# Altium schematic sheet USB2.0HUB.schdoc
size 311 x 219 mm
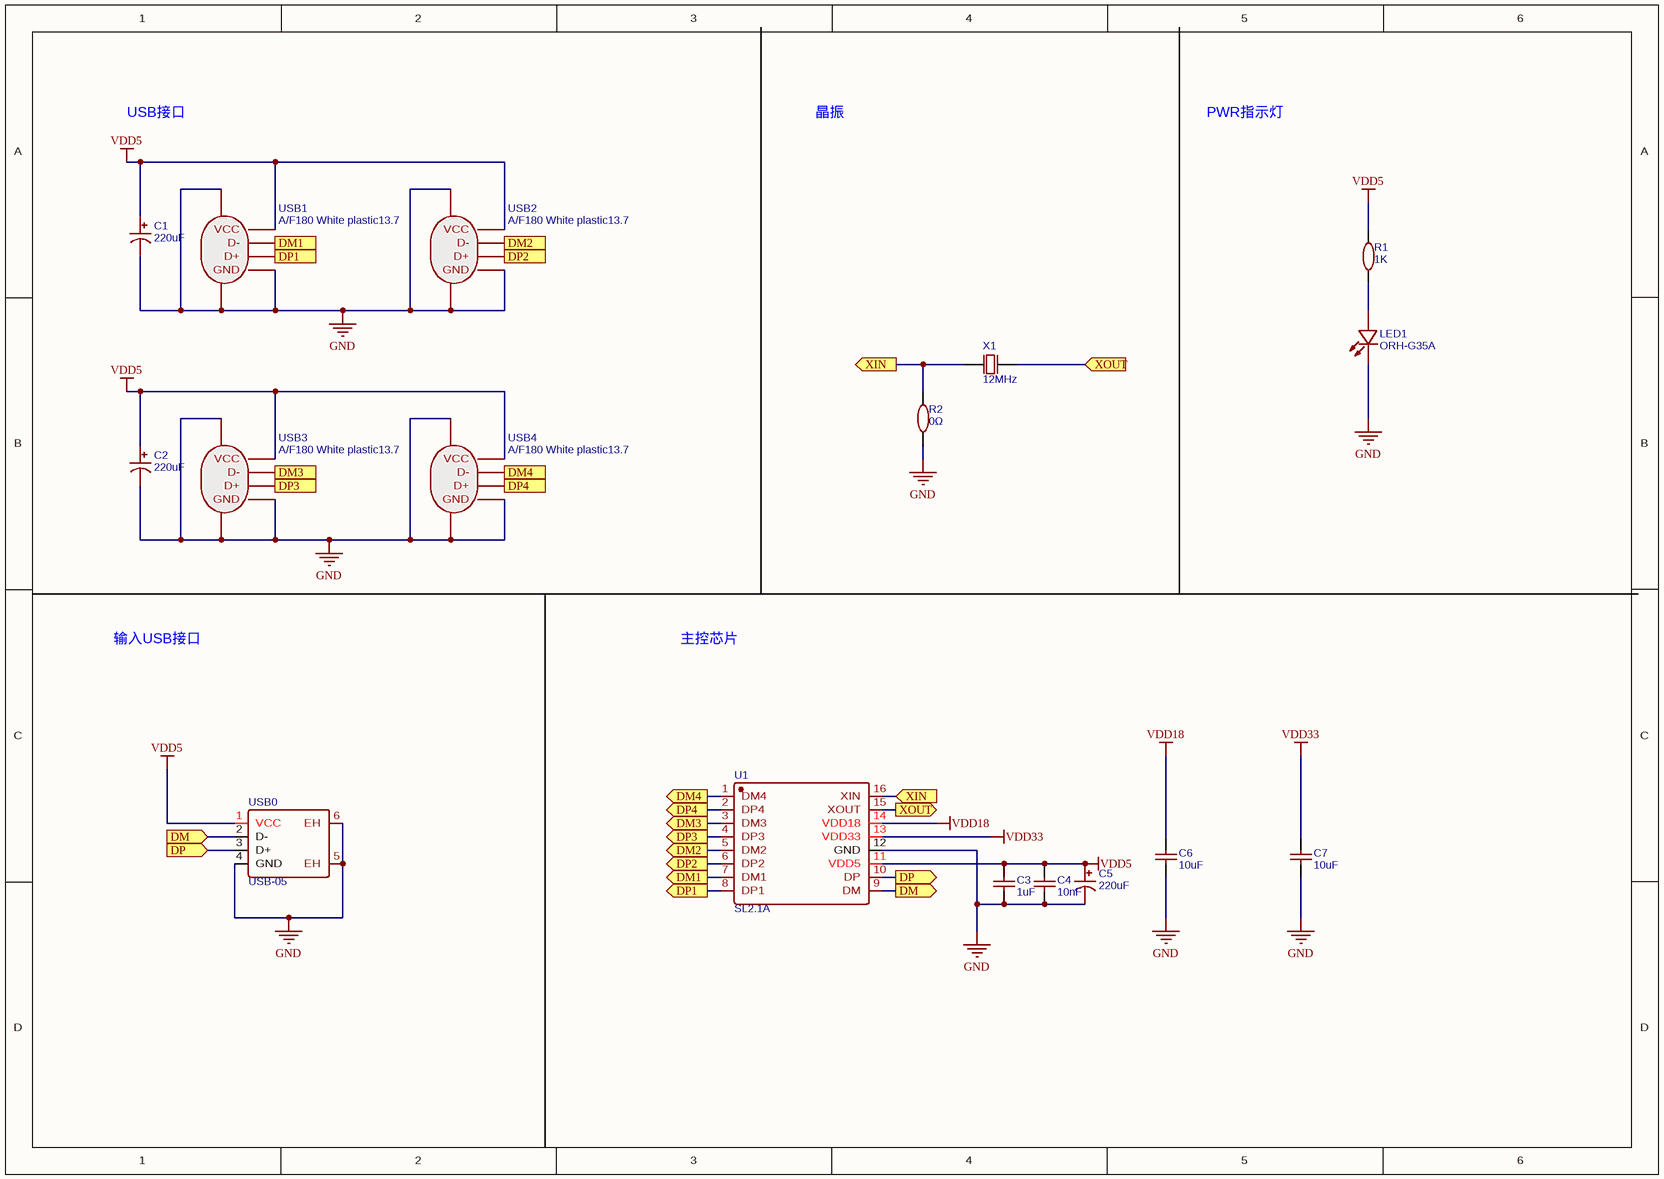
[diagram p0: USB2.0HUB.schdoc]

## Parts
C1  220uF  [CAP-SMD_BD6.3-L6.6-W6.6-FD]
C2  220uF  [CAP-SMD_BD6.3-L6.6-W6.6-FD]
C3  1uF  [C0805]
C4  10nF  [C0805]
C5  220uF  [CAP-SMD_BD6.3-L6.6-W6.6-FD]
C6  10uF  [C0805]
C7  10uF  [C0805]
LED1  ORH-G35A  [LED0805-R-RD]
R1  1K  [R0805]
R2  0Ω  [R0805]
U1  SL2.1A  [SOP-16_L10.0-W3.9-P1.27-LS6.0-BL]
USB0  USB-05  [USB-A-TH_48037-0001]
USB1  A/F180 White plastic13.7  [USB-A-TH_USB-M-22]
USB2  A/F180 White plastic13.7  [USB-A-TH_USB-M-22]
USB3  A/F180 White plastic13.7  [USB-A-TH_USB-M-22]
USB4  A/F180 White plastic13.7  [USB-A-TH_USB-M-22]
X1  12MHz  [HC-49US_L11.5-W4.5-P4.88]

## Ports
DM1 (in), DM1 (out), DM2 (in), DM2 (out), DM3 (in), DM3 (out), DM4 (in), DM4 (out), DM (in), DM (out), DP1 (in), DP1 (out), DP2 (in), DP2 (out), DP3 (in), DP3 (out), DP4 (in), DP4 (out), DP (in), DP (out), XIN (in), XIN (out), XOUT (in), XOUT (out)

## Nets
GND: C1.2 C2.2 C3.1 C4.1 C5.2 C6.1 C7.1 LED1.2(C) R2.1 U1.12(GND) USB0.4(GND) USB0.5(EH) USB0.6(EH) USB1.0 USB1.4(GND) USB2.0 USB2.4(GND) USB3.0 USB3.4(GND) USB4.0 USB4.4(GND)
VDD5: C1.1 C2.1 C3.2 C4.2 C5.1 R1.2 U1.11(VDD5) USB0.1(VCC) USB1.1(VCC) USB2.1(VCC) USB3.1(VCC) USB4.1(VCC)
VDD18: C6.2 U1.14(VDD18)
VDD33: C7.2 U1.13(VDD33)
DM: U1.9(DM) USB0.2(D-) ; port DM
DM1: U1.7(DM1) USB1.2(D-) ; port DM1
DM2: U1.5(DM2) USB2.2(D-) ; port DM2
DM3: U1.3(DM3) USB3.2(D-) ; port DM3
DM4: U1.1(DM4) USB4.2(D-) ; port DM4
DP: U1.10(DP) USB0.3(D+) ; port DP
DP1: U1.8(DP1) USB1.3(D+) ; port DP1
DP2: U1.6(DP2) USB2.3(D+) ; port DP2
DP3: U1.4(DP3) USB3.3(D+) ; port DP3
DP4: U1.2(DP4) USB4.3(D+) ; port DP4
XIN: R2.2 U1.16(XIN) X1.1(OSC1) ; port XIN
XOUT: U1.15(XOUT) X1.2(OSC2) ; port XOUT
NetLED1_1: LED1.1(A) R1.1

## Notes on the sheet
- USB接口
- 晶振
- PWR指示灯
- 输入USB接口
- 主控芯片

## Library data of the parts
C1 C2 C5 = 220uF: BOM_Manufacturer: ROQANG; BOM_Manufacturer Part: RVT1C221M0607; nameAlias: Capacitance
C3 C4 C6 C7 = 1uF: BOM_Manufacturer Part: CL21F105ZOFNNNE; BOM_Manufacturer: SAMSUNG; nameAlias: Capacitance
LED1 = ORH-G35A: BOM_Manufacturer: Orient; Contributor: LCSC; SMT Type: Extend
R1 R2 = 1K: BOM_Manufacturer: UniOhm; BOM_Manufacturer Part: 0805W8J0102T5E; nameAlias: Resistance (Ohms)
U1 = SL2.1A: BOM_Manufacturer: CoreChips; Contributor: LCSC; SMT Type: Extend
USB0 = USB-05: BOM_Manufacturer: SOFNG; Contributor: LCSC
USB1-USB4 = A/F180 White plastic13.7: BOM_Manufacturer: ValuePro
X1 = 12MHz: BOM_Manufacturer: Yangxing Tech; BOM_Manufacturer Part: X49SD12MSD2SI; nameAlias: Frequency; Contributor: LCSC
